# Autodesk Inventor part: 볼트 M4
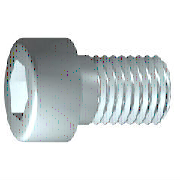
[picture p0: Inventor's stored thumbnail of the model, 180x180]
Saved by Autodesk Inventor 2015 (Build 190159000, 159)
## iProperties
IsCustomPart: 0
Created: 2012-02
Part Number: 볼트 M4
Material: 강철, 연강
Description: 6각 소켓 머리 캡 나사
Document SubType Name: Modeling
Standard: ISO 4762
Designer: mduedu
Standard Revision: Fourth edition 2004-03-01
Standards Organization: ISO
Language: ko-KR
Size Designation: M4 x 12
Categories: <MemberInstance><Categories><Category DisplayName="조임쇠" InternalName="e4da775c-781d-43d5-af7c-5136215cf5a6" Mnemonic="FSTN"><Category DisplayName="볼트" InternalN
Density: 7.75 g/cm^3
Appearance: 강철
Author: mduedu
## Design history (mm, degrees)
sketch "스케치1"
  geometry: L1 (-1, 0)-(12, 0); L2 (12, 0)-(12, 2); L3 (12, 2)-(1.75, 2); L4 (1.75, 2)-(1.32, 2); L5 (1.32, 2)-(0, 2); L6 (0, 2)-(0, 3.5); L7 (0, 3.5)-(-4, 3.5); L8 (-4, 3.5)-(-4, 1.732); L9 (-4, 1.732)-(-2, 1.732); L10 (-2, 1.732)-(-1, 0); L11 (-7.2, 0)-(15.2, 0) reference; L12 (0, -0.7)-(0, 4.2) reference; L13 (1.75, 2)-(0, 2)
  constraints: 22 end point, 6 parallel, 2 collinear, 2 perpendicular, 1 horizontal, 1 point on line
  dimensions: "d1" = 10.25 distance from line of L3.end L2 (= GEL); "d2" = 0.42952 distance of L4.end L3.end (computed from GAL); "d3" = 4 distance between parallel lines of L8 L6 (= KOH); "d4" = 2 distance of L8.end L9.end (= INTI); "d5" = 60 deg angle of L10 L1; "d6" = 4 diameter of L3 L1 (= GD); "d7" = 4 diameter of L5 L1 (= BDM); "d8" = 3.4641 diameter of L9 L1 (= 1.1547 x SW); "d9" = 7 diameter of L7 L1 (= KOD); "d26" = 12 distance between parallel lines of L12 L2 (= NLG)
revolve "본체" sketch "스케치1" stored, may be unused: angle "d10" = 90 deg
sketch "스케치2"
  geometry: L1 (0, -4.9)-(0, 4.9) reference; L2 (-4.9, 0)-(4.9, 0) reference; L3 (1.732, 0)-(0.866, -1.5); L4 (0.866, -1.5)-(-0.866, -1.5); L5 (-0.866, -1.5)-(-1.732, 0); L6 (-1.732, 0)-(-0.866, 1.5); L7 (-0.866, 1.5)-(0.866, 1.5); L8 (0.866, 1.5)-(1.732, 0); 2 further points
  constraints: 12 end point, 1 coincident, 1 horizontal alignment, 1 point on line, 12 other
extrude "슬롯" join sketch "스케치2" stored distance "d11" = 10; taper "d12" = 0 deg
workplane "Work Plane1"
fillet "Fillet2" dims "d30" = 0.1 (= R)
body "Solid1"
fillet "모깎기1" dims "d17" = 0.4 (= RR)
feature "스레드" dims "d13" = 10.25 (= GEL), "d14" = 0
chamfer "모따기1" distance "d15" = 0.42941 (= -0.5 x SPD + 0.5 x GD); stored, may be unused: second distance "d16" = 0.42941 (= GUL), angle "d27" = 45 deg
other parameters: "GD" = 4 [user parameter; used in 2 equation terms], "NLG" = 12 [user parameter; used in 1 equation term], "GEL" = 10.25 [user parameter; used in 2 equation terms], "KOD" = 7 [user parameter; used in 1 equation term], "KOH" = 4 [user parameter; used in 1 equation term], "INTI" = 2 [user parameter; used in 1 equation term], "GAL" = 0.42941 (= 0.61345 x PTC) [user parameter; used in 1 equation term], "GUL" = 0.42941 (= 0.61345 x PTC) [user parameter; used in 1 equation term], "BDM" = 4 (= NND) [user parameter; used in 1 equation term], "SW" = 3 [user parameter; used in 2 equation terms], "RR" = 0.4 [user parameter; used in 1 equation term], "SPD" = 3.14117 (= NND - 1.2269 x PTC) [user parameter; used in 1 equation term], "d19" = 0, "d28" = 0, "d29" = 0, "R" = 0.1 [user parameter; used in 1 equation term], "TOA" = 30 deg [user parameter], "GD1" = 3.14117 (= THREADDIA - 1.2269 x PTC) [user parameter], "THREADDIA" = 4 [user parameter; used in 1 equation term], "FAWI" = 45 deg [user parameter], "TPU" = 14.28571 (computed from PTC) [user parameter], "PTC" = 0.7 [user parameter; used in 5 equation terms], "NND" = 4 [user parameter; used in 2 equation terms], "E0" = 3.465 (= 1.155 x SW) [user parameter]
